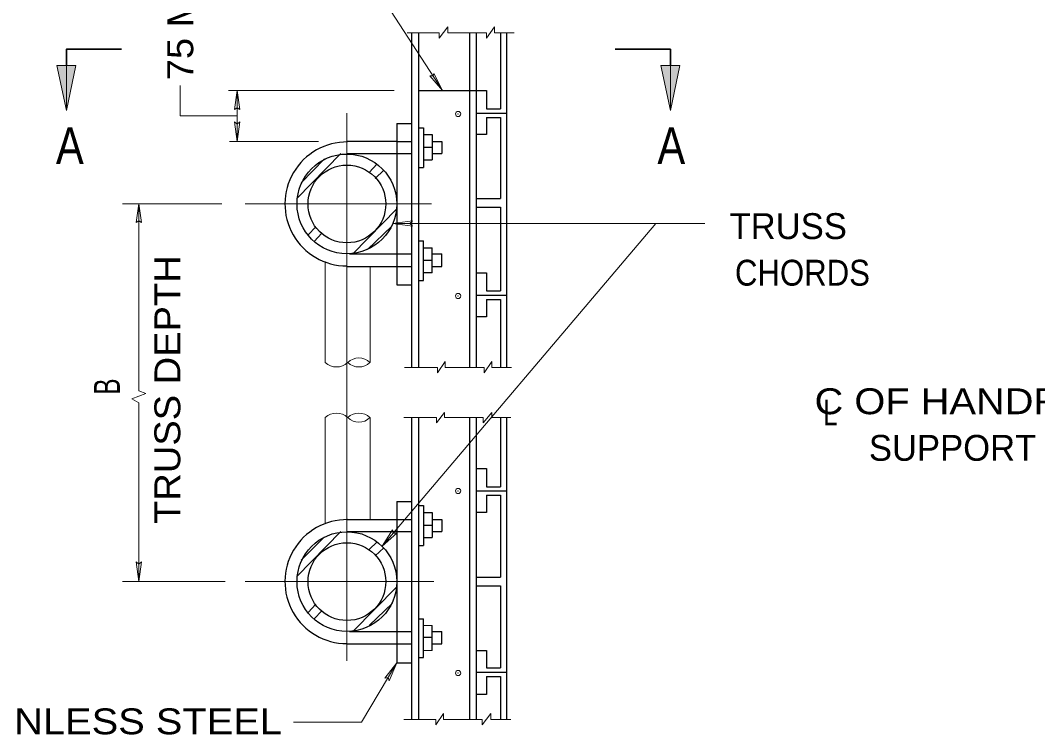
# Model space of a CAD drawing. Extents: x 312601.858 to 312602.699, y 144420.109 to 144420.704.
# Drawn here: x 312601.9235 to 312602.0414, y 144420.5352 to 144420.6179 of the extents above; entities that cross this region are included whole.
import ezdxf
from ezdxf.enums import TextEntityAlignment as Align

# ---------------------------------------------------------------- set-up
doc = ezdxf.new("R2010")
doc.units = 0
doc.header["$LTSCALE"] = 0.0012
doc.header["$PDMODE"] = 32
doc.header["$PDSIZE"] = 0.0006
doc.linetypes.add('DOT_DASHED', pattern=[7.7, 5, -1.2, 0.3, -1.2])
doc.linetypes.add('MEDIUM_DASHED', pattern=[4.5, 3, -1.5])
for name, color, linetype, lineweight in [('1', 7, 'Continuous', 13), ('2', 7, 'Continuous', 13), ('5', 7, 'Continuous', 25)]:
    doc.layers.add(name, color=color, linetype=linetype, lineweight=lineweight)

msp = doc.modelspace()

# ---------------------------------------------------------------- hatches: boundary and pattern name
at = {"layer": '1'}
for points in [[(312601.9277, 144420.6127), (312601.9288, 144420.6127), (312601.9288, 144420.6075)], [(312601.9299, 144420.6127), (312601.9288, 144420.6127), (312601.9288, 144420.6075)], [(312601.9977, 144420.6127), (312601.9988, 144420.6127), (312601.9988, 144420.6075)], [(312601.9999, 144420.6127), (312601.9988, 144420.6127), (312601.9988, 144420.6075)]]:
    msp.add_hatch(color=256, dxfattribs=at).paths.add_polyline_path(points)

# ---------------------------------------------------------------- linework, layer by layer
for p, q in [((312601.9586, 144420.6311), (312601.9724, 144420.6098)), ((312601.9683, 144420.6165), (312601.972, 144420.6165)), ((312601.972, 144420.6159), (312601.973, 144420.6172)), ((312601.972, 144420.6159), (312601.972, 144420.6165)), ((312601.973, 144420.6165), (312601.973, 144420.6172)), ((312601.973, 144420.6165), (312601.9775, 144420.6165)), ((312601.9775, 144420.6159), (312601.9784, 144420.6172)), ((312601.9775, 144420.6159), (312601.9775, 144420.6165)), ((312601.9784, 144420.6165), (312601.9784, 144420.6172)), ((312601.9784, 144420.6165), (312601.9807, 144420.6165)), ((312601.9288, 144420.6077), (312601.9288, 144420.6145)), ((312601.9988, 144420.6077), (312601.9988, 144420.6145)), ((312601.942, 144420.6104), (312601.942, 144420.6069)), ((312601.9476, 144420.6098), (312601.9668, 144420.6098)), ((312601.9486, 144420.6098), (312601.9486, 144420.6039)), ((312601.958, 144420.6039), (312601.9477, 144420.6039)), ((312601.9555, 144420.5973), (312601.9606, 144420.6025)), ((312601.956, 144420.5991), (312601.9587, 144420.6019)), ((312601.9639, 144420.6003), (312601.9648, 144420.6013)), ((312601.9646, 144420.5996), (312601.9656, 144420.6006)), ((312601.9353, 144420.5967), (312601.9468, 144420.5967)), ((312601.9372, 144420.5967), (312601.9372, 144420.575)), ((312601.962, 144420.5909), (312601.9671, 144420.5961)), ((312601.9568, 144420.5931), (312601.9577, 144420.594)), ((312601.9637, 144420.5914), (312601.9665, 144420.5941)), ((312601.9654, 144420.557), (312601.9971, 144420.5944)), ((312601.9666, 144420.5944), (312602.0028, 144420.5944)), ((312601.9575, 144420.5923), (312601.9584, 144420.5933)), ((312601.9588, 144420.59), (312601.9588, 144420.5783)), ((312601.964, 144420.5894), (312601.964, 144420.5783)), ((312601.968, 144420.5777), (312601.9718, 144420.5777)), ((312601.9718, 144420.5771), (312601.9727, 144420.5784)), ((312601.9718, 144420.5771), (312601.9718, 144420.5777)), ((312601.9727, 144420.5777), (312601.9727, 144420.5784)), ((312601.9727, 144420.5777), (312601.9772, 144420.5777)), ((312601.9772, 144420.5771), (312601.9781, 144420.5784)), ((312601.9772, 144420.5771), (312601.9772, 144420.5777)), ((312601.9781, 144420.5777), (312601.9781, 144420.5784)), ((312601.9781, 144420.5777), (312601.9804, 144420.5777)), ((312601.9372, 144420.5736), (312601.9372, 144420.5529)), ((312601.9588, 144420.5596), (312601.9588, 144420.5719)), ((312601.964, 144420.5601), (312601.964, 144420.5719)), ((312601.9679, 144420.5719), (312601.9717, 144420.5719)), ((312601.9717, 144420.5713), (312601.9726, 144420.5725)), ((312601.9717, 144420.5713), (312601.9717, 144420.5719)), ((312601.9726, 144420.5719), (312601.9726, 144420.5725)), ((312601.9726, 144420.5719), (312601.9771, 144420.5719)), ((312601.9771, 144420.5713), (312601.9781, 144420.5725)), ((312601.9771, 144420.5713), (312601.9771, 144420.5719)), ((312601.9781, 144420.5719), (312601.9781, 144420.5725)), ((312601.9781, 144420.5719), (312601.9803, 144420.5719)), ((312601.9555, 144420.5535), (312601.9606, 144420.5587)), ((312601.956, 144420.5554), (312601.9587, 144420.5581)), ((312601.9639, 144420.5566), (312601.9648, 144420.5575)), ((312601.9646, 144420.5559), (312601.9656, 144420.5568)), ((312601.9353, 144420.5529), (312601.9472, 144420.5529)), ((312601.962, 144420.5471), (312601.9671, 144420.5523)), ((312601.9568, 144420.5493), (312601.9577, 144420.5503)), ((312601.9639, 144420.5478), (312601.9666, 144420.5504)), ((312601.9575, 144420.5486), (312601.9584, 144420.5495)), ((312601.9702, 144420.5478), (312601.9712, 144420.5478)), ((312601.9712, 144420.5449), (312601.9702, 144420.5449)), ((312601.9671, 144420.5435), (312601.963, 144420.5366)), ((312601.9716, 144420.5363), (312601.9725, 144420.5376)), ((312601.9725, 144420.5369), (312601.9725, 144420.5376)), ((312601.977, 144420.5363), (312601.978, 144420.5376)), ((312601.978, 144420.5369), (312601.978, 144420.5376)), ((312601.9551, 144420.5366), (312601.963, 144420.5366)), ((312601.9679, 144420.5369), (312601.9716, 144420.5369)), ((312601.9716, 144420.5363), (312601.9716, 144420.5369)), ((312601.9725, 144420.5369), (312601.977, 144420.5369)), ((312601.977, 144420.5363), (312601.977, 144420.5369)), ((312601.978, 144420.5369), (312601.9803, 144420.5369))]:
    msp.add_line(p, q, dxfattribs=at)
at = {"layer": '1', "lineweight": 25}
for p, q in [((312601.9688, 144420.6165), (312601.9688, 144420.5777)), ((312601.9696, 144420.6165), (312601.9696, 144420.5777)), ((312601.9755, 144420.6165), (312601.9755, 144420.5777)), ((312601.9763, 144420.6165), (312601.9763, 144420.5777)), ((312601.9791, 144420.6165), (312601.9791, 144420.6077)), ((312601.9798, 144420.6165), (312601.9798, 144420.5777)), ((312601.9696, 144420.6098), (312601.9775, 144420.6098)), ((312601.9775, 144420.6098), (312601.9775, 144420.6077)), ((312601.9775, 144420.6077), (312601.9791, 144420.6077)), ((312601.9671, 144420.606), (312601.9688, 144420.606)), ((312601.9671, 144420.606), (312601.9671, 144420.5873)), ((312601.9775, 144420.6067), (312601.9791, 144420.6067)), ((312601.9775, 144420.6067), (312601.9775, 144420.6047)), ((312601.9791, 144420.6067), (312601.9791, 144420.5973)), ((312601.9702, 144420.6047), (312601.9712, 144420.6047)), ((312601.9712, 144420.6047), (312601.9712, 144420.6018)), ((312601.9775, 144420.6047), (312601.9763, 144420.6047)), ((312601.967, 144420.6039), (312601.9613, 144420.6039)), ((312601.9712, 144420.6032), (312601.9702, 144420.6032)), ((312601.9712, 144420.6039), (312601.9723, 144420.6039)), ((312601.9723, 144420.6039), (312601.9723, 144420.6025)), ((312601.9613, 144420.6025), (312601.9671, 144420.6025)), ((312601.9712, 144420.6025), (312601.9723, 144420.6025)), ((312601.9696, 144420.6009), (312601.9702, 144420.6009)), ((312601.9702, 144420.6018), (312601.9712, 144420.6018)), ((312601.9763, 144420.5973), (312601.9791, 144420.5973)), ((312601.9763, 144420.5963), (312601.9791, 144420.5963)), ((312601.9791, 144420.5963), (312601.9791, 144420.5866)), ((312601.9696, 144420.5924), (312601.9702, 144420.5924)), ((312601.9702, 144420.5916), (312601.9712, 144420.5916)), ((312601.9712, 144420.5887), (312601.9712, 144420.5916)), ((312601.9616, 144420.5909), (312601.9671, 144420.5909)), ((312601.9712, 144420.5909), (312601.9723, 144420.5909)), ((312601.9723, 144420.5894), (312601.9723, 144420.5909)), ((312601.9613, 144420.5894), (312601.9671, 144420.5894)), ((312601.9712, 144420.5901), (312601.9702, 144420.5901)), ((312601.9712, 144420.5894), (312601.9723, 144420.5894)), ((312601.9712, 144420.5887), (312601.9702, 144420.5887)), ((312601.9763, 144420.5887), (312601.9775, 144420.5887)), ((312601.9775, 144420.5887), (312601.9775, 144420.5866)), ((312601.9671, 144420.5873), (312601.9688, 144420.5873)), ((312601.9763, 144420.5861), (312601.9798, 144420.5861)), ((312601.9775, 144420.5866), (312601.9791, 144420.5866)), ((312601.9775, 144420.5856), (312601.9791, 144420.5856)), ((312601.9775, 144420.5856), (312601.9775, 144420.5836)), ((312601.9791, 144420.5856), (312601.9791, 144420.5777)), ((312601.9775, 144420.5836), (312601.9763, 144420.5836)), ((312601.9688, 144420.5719), (312601.9688, 144420.5369)), ((312601.9696, 144420.5719), (312601.9696, 144420.5369)), ((312601.9755, 144420.5719), (312601.9755, 144420.5369)), ((312601.9763, 144420.5719), (312601.9763, 144420.5369)), ((312601.9791, 144420.5719), (312601.9791, 144420.5639)), ((312601.9798, 144420.5719), (312601.9798, 144420.5369)), ((312601.9763, 144420.566), (312601.9775, 144420.566)), ((312601.9775, 144420.566), (312601.9775, 144420.5639)), ((312601.9763, 144420.5634), (312601.9798, 144420.5634)), ((312601.9775, 144420.5639), (312601.9791, 144420.5639)), ((312601.9671, 144420.5622), (312601.9688, 144420.5622)), ((312601.9671, 144420.5622), (312601.9671, 144420.5435)), ((312601.9775, 144420.5629), (312601.9791, 144420.5629)), ((312601.9775, 144420.5629), (312601.9775, 144420.5609)), ((312601.9791, 144420.5629), (312601.9791, 144420.5534)), ((312601.9702, 144420.5609), (312601.9712, 144420.5609)), ((312601.9712, 144420.5609), (312601.9712, 144420.558)), ((312601.9775, 144420.5609), (312601.9763, 144420.5609)), ((312601.9613, 144420.5601), (312601.9671, 144420.5601)), ((312601.9712, 144420.5601), (312601.9723, 144420.5601)), ((312601.9723, 144420.5601), (312601.9723, 144420.5587)), ((312601.9613, 144420.5587), (312601.9671, 144420.5587)), ((312601.9712, 144420.5594), (312601.9702, 144420.5594)), ((312601.9712, 144420.5587), (312601.9723, 144420.5587)), ((312601.9702, 144420.558), (312601.9712, 144420.558)), ((312601.9696, 144420.5571), (312601.9702, 144420.5571)), ((312601.9763, 144420.5534), (312601.9791, 144420.5534)), ((312601.9763, 144420.5524), (312601.9791, 144420.5524)), ((312601.9791, 144420.5524), (312601.9791, 144420.5429)), ((312601.9696, 144420.5486), (312601.9702, 144420.5486)), ((312601.9712, 144420.5449), (312601.9712, 144420.5478)), ((312601.9616, 144420.5471), (312601.9671, 144420.5471)), ((312601.9712, 144420.5471), (312601.9723, 144420.5471)), ((312601.9723, 144420.5457), (312601.9723, 144420.5471)), ((312601.9613, 144420.5457), (312601.9671, 144420.5457)), ((312601.9712, 144420.5464), (312601.9702, 144420.5464)), ((312601.9712, 144420.5457), (312601.9723, 144420.5457)), ((312601.9763, 144420.5449), (312601.9775, 144420.5449)), ((312601.9775, 144420.5449), (312601.9775, 144420.5429)), ((312601.9671, 144420.5435), (312601.9688, 144420.5435)), ((312601.9763, 144420.5424), (312601.9798, 144420.5424)), ((312601.9775, 144420.5429), (312601.9791, 144420.5429)), ((312601.9775, 144420.5419), (312601.9791, 144420.5419)), ((312601.9775, 144420.5419), (312601.9775, 144420.5398)), ((312601.9791, 144420.5419), (312601.9791, 144420.5369)), ((312601.9775, 144420.5398), (312601.9763, 144420.5398))]:
    msp.add_line(p, q, dxfattribs=at)
at = {"layer": '1', "linetype": 'DOT_DASHED'}
for p, q in [((312601.9613, 144420.6072), (312601.9613, 144420.5437)), ((312601.9495, 144420.5967), (312601.9711, 144420.5967)), ((312601.9495, 144420.5529), (312601.9714, 144420.5529))]:
    msp.add_line(p, q, dxfattribs=at)
at = {"layer": '1', "linetype": 'MEDIUM_DASHED', "lineweight": 25}
for p, q in [((312601.9671, 144420.6039), (312601.9688, 144420.6039)), ((312601.9671, 144420.6025), (312601.9688, 144420.6025)), ((312601.9671, 144420.5909), (312601.9688, 144420.5909)), ((312601.9671, 144420.5894), (312601.9688, 144420.5894)), ((312601.9671, 144420.5601), (312601.9688, 144420.5601)), ((312601.9671, 144420.5587), (312601.9688, 144420.5587)), ((312601.9671, 144420.5471), (312601.9688, 144420.5471)), ((312601.9671, 144420.5457), (312601.9688, 144420.5457))]:
    msp.add_line(p, q, dxfattribs=at)
at = {"layer": '1', "lineweight": 35}
for points in [[(312601.9288, 144420.6127), (312601.9288, 144420.6146), (312601.9352, 144420.6146)], [(312601.9988, 144420.6127), (312601.9988, 144420.6146), (312601.9924, 144420.6146)]]:
    msp.add_lwpolyline(points, dxfattribs=at)
at = {"layer": '1'}
for points in [[(312601.9277, 144420.6127), (312601.9288, 144420.6127), (312601.9288, 144420.6075)], [(312601.9299, 144420.6127), (312601.9288, 144420.6127), (312601.9288, 144420.6075)], [(312601.9977, 144420.6127), (312601.9988, 144420.6127), (312601.9988, 144420.6075)], [(312601.9999, 144420.6127), (312601.9988, 144420.6127), (312601.9988, 144420.6075)], [(312601.9714, 144420.6118), (312601.9724, 144420.6098), (312601.9709, 144420.6115), (312601.9713, 144420.6115)], [(312601.9483, 144420.6076), (312601.9486, 144420.6098), (312601.9489, 144420.6076), (312601.9486, 144420.6078)], [(312601.9489, 144420.6062), (312601.9486, 144420.6039), (312601.9483, 144420.6062), (312601.9486, 144420.6059)], [(312601.9369, 144420.5945), (312601.9372, 144420.5967), (312601.9375, 144420.5945), (312601.9372, 144420.5947)], [(312601.9689, 144420.5941), (312601.9666, 144420.5944), (312601.9689, 144420.5947), (312601.9686, 144420.5944)], [(312601.9671, 144420.5585), (312601.9654, 144420.557), (312601.9666, 144420.5589), (312601.9667, 144420.5585)], [(312601.9375, 144420.5552), (312601.9372, 144420.5529), (312601.9369, 144420.5552), (312601.9372, 144420.5549)], [(312601.9657, 144420.5417), (312601.9671, 144420.5435), (312601.9662, 144420.5414), (312601.9661, 144420.5418)]]:
    msp.add_lwpolyline(points, close=True, dxfattribs=at)
at = {"layer": '1', "lineweight": 25}
for points in [[(312601.9696, 144420.6055), (312601.9702, 144420.6055), (312601.9702, 144420.6009)], [(312601.9696, 144420.5878), (312601.9702, 144420.5878), (312601.9702, 144420.5924)], [(312601.9696, 144420.5617), (312601.9702, 144420.5617), (312601.9702, 144420.5571)], [(312601.9696, 144420.5441), (312601.9702, 144420.5441), (312601.9702, 144420.5486)]]:
    msp.add_lwpolyline(points, dxfattribs=at)
for centre, radius in [((312601.961305, 144420.59667), 0.00578), ((312601.961305, 144420.59667), 0.004505), ((312601.961305, 144420.552895), 0.00578), ((312601.961305, 144420.552895), 0.004505)]:
    msp.add_circle(centre, radius, dxfattribs=at)
for centre in [(312601.961305, 144420.59667), (312601.961305, 144420.552895)]:
    msp.add_arc(centre, 0.007183, 89.32408, 269.97928, dxfattribs=at)
at = {"layer": '1'}
for p in [(312601.9742, 144420.6071), (312601.9742, 144420.586), (312601.9742, 144420.5634), (312601.9742, 144420.5423)]:
    msp.add_point(p, dxfattribs=at)
at = {"layer": '2'}
msp.add_line((312601.9486, 144420.6069), (312601.942, 144420.6069), dxfattribs=at)
at = {"layer": '2', "lineweight": 25}
msp.add_line((312601.9763, 144420.6072), (312601.9798, 144420.6072), dxfattribs=at)
at = {"layer": '2'}
for centre, major_axis, start_param, end_param in [((312601.96265, 144420.57699), (-0.001351, -0.001289), 3.1574249, 4.712389), ((312601.96005, 144420.57961), (0.001351, -0.001289), 4.712389, 6.2673531), ((312601.96265, 144420.57961), (0.001351, -0.001289), 4.712389, 6.2673531), ((312601.96005, 144420.57059), (-0.001351, -0.001289), 3.1574249, 4.712389), ((312601.96265, 144420.57059), (-0.001351, -0.001289), 3.1574249, 4.712389), ((312601.96265, 144420.57321), (0.001351, -0.001289), 4.712389, 6.2673531)]:
    msp.add_ellipse(centre, major_axis=major_axis, ratio=0.969426, start_param=start_param, end_param=end_param, dxfattribs=at)
at = {"layer": '5', "lineweight": 13}
msp.add_lwpolyline([(312601.9372, 144420.5736), (312601.9364, 144420.5741), (312601.938, 144420.5747), (312601.9372, 144420.575)], dxfattribs=at)

# ---------------------------------------------------------------- texts
at = {"layer": '2'}
for s, height, width, p in [('75 MM', 0.003, 1.1, (312601.9435, 144420.61775)), ('TRUSS DEPTH', 0.002999, 1.1, (312601.942, 144420.57515)), ('B', 0.003, 0.7, (312601.935, 144420.5755))]:
    msp.add_text(s, height=height, rotation=90, dxfattribs=dict(at, width=width)).set_placement(p, align=Align.CENTER)
for s, height, width, p in [('A', 0.00425, 0.85, (312601.9292, 144420.6013)), ('A', 0.00425, 0.85, (312601.9989, 144420.6013)), ('CHORDS', 0.003, 0.9, (312602.0141, 144420.5872))]:
    msp.add_text(s, height=height, dxfattribs=dict(at, width=width)).set_placement(p, align=Align.CENTER)
msp.add_text('TRUSS', height=0.003, dxfattribs=at).set_placement((312602.01245, 144420.5926), align=Align.CENTER)
at = {"layer": '2', "width": 1.15}
for s, p in [('C OF HANDRAIL ', (312602.0155, 144420.5723)), ('STAINLESS STEEL', (312601.9125, 144420.5352))]:
    msp.add_text(s, height=0.003, dxfattribs=at).set_placement(p)
at = {"layer": '2'}
msp.add_text('SUPPORT', height=0.003, dxfattribs=at).set_placement((312602.0218, 144420.5669))
at = {"layer": '5', "width": 0.75}
msp.add_text('L', height=0.003, dxfattribs=at).set_placement((312602.0165, 144420.571))

doc.saveas('drawing.dxf')
